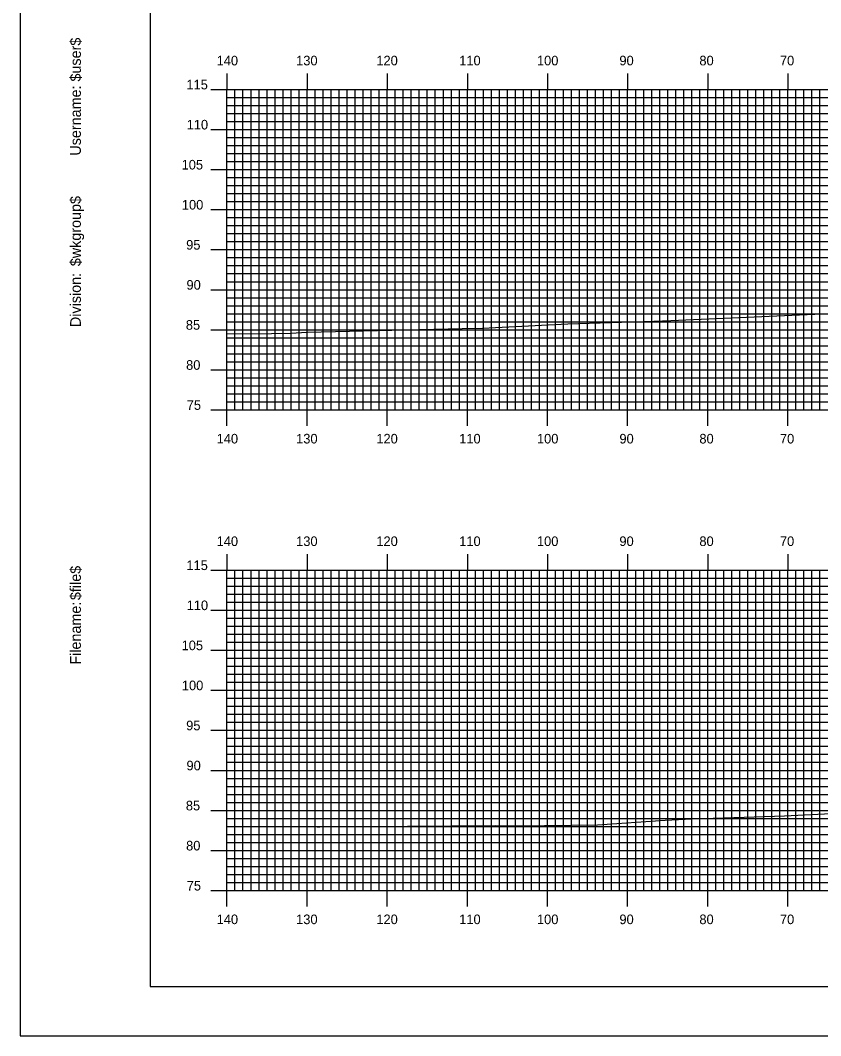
# Model space of a CAD drawing. Extents: x 1760217 to 1760560, y 442591 to 442811.
# Drawn here: x 1760216.9 to 1760316.8, y 442590.5 to 442717.3 of the extents above; entities that cross this region are included whole.
import ezdxf

# ---------------------------------------------------------------- set-up
doc = ezdxf.new("R2010")
doc.units = 0
for name, color, linetype in [('BORDER', 7, 'Continuous'), ('H_V ANNOTATION', 7, 'Continuous'), ('MAJOR', 7, 'Continuous'), ('MINOR', 7, 'Continuous'), ('PLOT BOUNDARY', 7, 'Continuous'), ('S_Roadway_Centerline', 7, 'Continuous')]:
    doc.layers.add(name, color=color, linetype=linetype)

msp = doc.modelspace()

# ---------------------------------------------------------------- linework, layer by layer
at = {"layer": 'BORDER'}
msp.add_lwpolyline([(1760233.1, 442596.67), (1760553.1, 442596.67), (1760553.1, 442806.67), (1760233.1, 442806.67)], close=True, dxfattribs=at)
at = {"layer": 'MAJOR'}
for p, q in [((1760242.7, 442710.67), (1760242.7, 442708.67)), ((1760252.7, 442710.67), (1760252.7, 442708.67)), ((1760262.7, 442710.67), (1760262.7, 442708.67)), ((1760272.7, 442710.67), (1760272.7, 442708.67)), ((1760282.7, 442710.67), (1760282.7, 442708.67)), ((1760292.7, 442710.67), (1760292.7, 442708.67)), ((1760302.7, 442710.67), (1760302.7, 442708.67)), ((1760312.7, 442710.67), (1760312.7, 442708.67)), ((1760240.7, 442708.67), (1760242.7, 442708.67)), ((1760242.7, 442708.67), (1760522.7, 442708.67)), ((1760242.7, 442668.67), (1760242.7, 442708.67)), ((1760242.7, 442668.67), (1760242.7, 442708.67)), ((1760242.7, 442708.67), (1760522.7, 442708.67)), ((1760252.7, 442668.67), (1760252.7, 442708.67)), ((1760262.7, 442668.67), (1760262.7, 442708.67)), ((1760272.7, 442668.67), (1760272.7, 442708.67)), ((1760282.7, 442668.67), (1760282.7, 442708.67)), ((1760292.7, 442668.67), (1760292.7, 442708.67)), ((1760302.7, 442668.67), (1760302.7, 442708.67)), ((1760312.7, 442668.67), (1760312.7, 442708.67)), ((1760240.7, 442703.67), (1760242.7, 442703.67)), ((1760242.7, 442703.67), (1760522.7, 442703.67)), ((1760240.7, 442698.67), (1760242.7, 442698.67)), ((1760242.7, 442698.67), (1760522.7, 442698.67)), ((1760240.7, 442693.67), (1760242.7, 442693.67)), ((1760242.7, 442693.67), (1760522.7, 442693.67)), ((1760240.7, 442688.67), (1760242.7, 442688.67)), ((1760242.7, 442688.67), (1760522.7, 442688.67)), ((1760240.7, 442683.67), (1760242.7, 442683.67)), ((1760242.7, 442683.67), (1760522.7, 442683.67)), ((1760240.7, 442678.67), (1760242.7, 442678.67)), ((1760242.7, 442678.67), (1760522.7, 442678.67)), ((1760240.7, 442673.67), (1760242.7, 442673.67)), ((1760242.7, 442673.67), (1760522.7, 442673.67)), ((1760240.7, 442668.67), (1760242.7, 442668.67)), ((1760242.7, 442668.67), (1760522.7, 442668.67)), ((1760242.7, 442668.67), (1760522.7, 442668.67)), ((1760242.7, 442666.66), (1760242.7, 442668.67)), ((1760252.7, 442666.66), (1760252.7, 442668.67)), ((1760262.7, 442666.66), (1760262.7, 442668.67)), ((1760272.7, 442666.66), (1760272.7, 442668.67)), ((1760282.7, 442666.66), (1760282.7, 442668.67)), ((1760292.7, 442666.66), (1760292.7, 442668.67)), ((1760302.7, 442666.66), (1760302.7, 442668.67)), ((1760312.7, 442666.66), (1760312.7, 442668.67)), ((1760242.7, 442650.67), (1760242.7, 442648.67)), ((1760252.7, 442650.67), (1760252.7, 442648.67)), ((1760262.7, 442650.67), (1760262.7, 442648.67)), ((1760272.7, 442650.67), (1760272.7, 442648.67)), ((1760282.7, 442650.67), (1760282.7, 442648.67)), ((1760292.7, 442650.67), (1760292.7, 442648.67)), ((1760302.7, 442650.67), (1760302.7, 442648.67)), ((1760312.7, 442650.67), (1760312.7, 442648.67)), ((1760240.7, 442648.67), (1760242.7, 442648.67)), ((1760242.7, 442648.67), (1760522.7, 442648.67)), ((1760242.7, 442608.67), (1760242.7, 442648.67)), ((1760242.7, 442608.67), (1760242.7, 442648.67)), ((1760242.7, 442648.67), (1760522.7, 442648.67)), ((1760252.7, 442608.67), (1760252.7, 442648.67)), ((1760262.7, 442608.67), (1760262.7, 442648.67)), ((1760272.7, 442608.67), (1760272.7, 442648.67)), ((1760282.7, 442608.67), (1760282.7, 442648.67)), ((1760292.7, 442608.67), (1760292.7, 442648.67)), ((1760302.7, 442608.67), (1760302.7, 442648.67)), ((1760312.7, 442608.67), (1760312.7, 442648.67)), ((1760240.7, 442643.67), (1760242.7, 442643.67)), ((1760242.7, 442643.67), (1760522.7, 442643.67)), ((1760240.7, 442638.67), (1760242.7, 442638.67)), ((1760242.7, 442638.67), (1760522.7, 442638.67)), ((1760240.7, 442633.67), (1760242.7, 442633.67)), ((1760242.7, 442633.67), (1760522.7, 442633.67)), ((1760240.7, 442628.67), (1760242.7, 442628.67)), ((1760242.7, 442628.67), (1760522.7, 442628.67)), ((1760240.7, 442623.67), (1760242.7, 442623.67)), ((1760242.7, 442623.67), (1760522.7, 442623.67)), ((1760240.7, 442618.67), (1760242.7, 442618.67)), ((1760242.7, 442618.67), (1760522.7, 442618.67)), ((1760240.7, 442613.67), (1760242.7, 442613.67)), ((1760242.7, 442613.67), (1760522.7, 442613.67)), ((1760240.7, 442608.67), (1760242.7, 442608.67)), ((1760242.7, 442608.67), (1760522.7, 442608.67)), ((1760242.7, 442608.67), (1760522.7, 442608.67)), ((1760242.7, 442606.66), (1760242.7, 442608.67)), ((1760252.7, 442606.66), (1760252.7, 442608.67)), ((1760262.7, 442606.66), (1760262.7, 442608.67)), ((1760272.7, 442606.66), (1760272.7, 442608.67)), ((1760282.7, 442606.66), (1760282.7, 442608.67)), ((1760292.7, 442606.66), (1760292.7, 442608.67)), ((1760302.7, 442606.66), (1760302.7, 442608.67)), ((1760312.7, 442606.66), (1760312.7, 442608.67))]:
    msp.add_line(p, q, dxfattribs=at)
at = {"layer": 'MINOR'}
for p, q in [((1760243.7, 442668.67), (1760243.7, 442708.67)), ((1760244.7, 442668.67), (1760244.7, 442708.67)), ((1760245.7, 442668.67), (1760245.7, 442708.67)), ((1760246.7, 442668.67), (1760246.7, 442708.67)), ((1760247.7, 442668.67), (1760247.7, 442708.67)), ((1760248.7, 442668.67), (1760248.7, 442708.67)), ((1760249.7, 442668.67), (1760249.7, 442708.67)), ((1760250.7, 442668.67), (1760250.7, 442708.67)), ((1760251.7, 442668.67), (1760251.7, 442708.67)), ((1760253.7, 442668.67), (1760253.7, 442708.67)), ((1760254.7, 442668.67), (1760254.7, 442708.67)), ((1760255.7, 442668.67), (1760255.7, 442708.67)), ((1760256.7, 442668.67), (1760256.7, 442708.67)), ((1760257.7, 442668.67), (1760257.7, 442708.67)), ((1760258.7, 442668.67), (1760258.7, 442708.67)), ((1760259.7, 442668.67), (1760259.7, 442708.67)), ((1760260.7, 442668.67), (1760260.7, 442708.67)), ((1760261.7, 442668.67), (1760261.7, 442708.67)), ((1760263.7, 442668.67), (1760263.7, 442708.67)), ((1760264.7, 442668.67), (1760264.7, 442708.67)), ((1760265.7, 442668.67), (1760265.7, 442708.67)), ((1760266.7, 442668.67), (1760266.7, 442708.67)), ((1760267.7, 442668.67), (1760267.7, 442708.67)), ((1760268.7, 442668.67), (1760268.7, 442708.67)), ((1760269.7, 442668.67), (1760269.7, 442708.67)), ((1760270.7, 442668.67), (1760270.7, 442708.67)), ((1760271.7, 442668.67), (1760271.7, 442708.67)), ((1760273.7, 442668.67), (1760273.7, 442708.67)), ((1760274.7, 442668.67), (1760274.7, 442708.67)), ((1760275.7, 442668.67), (1760275.7, 442708.67)), ((1760276.7, 442668.67), (1760276.7, 442708.67)), ((1760277.7, 442668.67), (1760277.7, 442708.67)), ((1760278.7, 442668.67), (1760278.7, 442708.67)), ((1760279.7, 442668.67), (1760279.7, 442708.67)), ((1760280.7, 442668.67), (1760280.7, 442708.67)), ((1760281.7, 442668.67), (1760281.7, 442708.67)), ((1760283.7, 442668.67), (1760283.7, 442708.67)), ((1760284.7, 442668.67), (1760284.7, 442708.67)), ((1760285.7, 442668.67), (1760285.7, 442708.67)), ((1760286.7, 442668.67), (1760286.7, 442708.67)), ((1760287.7, 442668.67), (1760287.7, 442708.67)), ((1760288.7, 442668.67), (1760288.7, 442708.67)), ((1760289.7, 442668.67), (1760289.7, 442708.67)), ((1760290.7, 442668.67), (1760290.7, 442708.67)), ((1760291.7, 442668.67), (1760291.7, 442708.67)), ((1760293.7, 442668.67), (1760293.7, 442708.67)), ((1760294.7, 442668.67), (1760294.7, 442708.67)), ((1760295.7, 442668.67), (1760295.7, 442708.67)), ((1760296.7, 442668.67), (1760296.7, 442708.67)), ((1760297.7, 442668.67), (1760297.7, 442708.67)), ((1760298.7, 442668.67), (1760298.7, 442708.67)), ((1760299.7, 442668.67), (1760299.7, 442708.67)), ((1760300.7, 442668.67), (1760300.7, 442708.67)), ((1760301.7, 442668.67), (1760301.7, 442708.67)), ((1760303.7, 442668.67), (1760303.7, 442708.67)), ((1760304.7, 442668.67), (1760304.7, 442708.67)), ((1760305.7, 442668.67), (1760305.7, 442708.67)), ((1760306.7, 442668.67), (1760306.7, 442708.67)), ((1760307.7, 442668.67), (1760307.7, 442708.67)), ((1760308.7, 442668.67), (1760308.7, 442708.67)), ((1760309.7, 442668.67), (1760309.7, 442708.67)), ((1760310.7, 442668.67), (1760310.7, 442708.67)), ((1760311.7, 442668.67), (1760311.7, 442708.67)), ((1760313.7, 442668.67), (1760313.7, 442708.67)), ((1760314.7, 442668.67), (1760314.7, 442708.67)), ((1760315.7, 442668.67), (1760315.7, 442708.67)), ((1760316.7, 442668.67), (1760316.7, 442708.67)), ((1760242.7, 442707.67), (1760522.7, 442707.67)), ((1760242.7, 442707.67), (1760244.7, 442707.67)), ((1760242.7, 442706.67), (1760522.7, 442706.67)), ((1760242.7, 442706.67), (1760244.7, 442706.67)), ((1760242.7, 442705.67), (1760522.7, 442705.67)), ((1760242.7, 442705.67), (1760244.7, 442705.67)), ((1760242.7, 442704.67), (1760522.7, 442704.67)), ((1760242.7, 442704.67), (1760244.7, 442704.67)), ((1760242.7, 442702.67), (1760522.7, 442702.67)), ((1760242.7, 442702.67), (1760244.7, 442702.67)), ((1760242.7, 442701.67), (1760522.7, 442701.67)), ((1760242.7, 442701.67), (1760244.7, 442701.67)), ((1760242.7, 442700.67), (1760522.7, 442700.67)), ((1760242.7, 442700.67), (1760244.7, 442700.67)), ((1760242.7, 442699.67), (1760522.7, 442699.67)), ((1760242.7, 442699.67), (1760244.7, 442699.67)), ((1760242.7, 442697.67), (1760522.7, 442697.67)), ((1760242.7, 442697.67), (1760244.7, 442697.67)), ((1760242.7, 442696.67), (1760522.7, 442696.67)), ((1760242.7, 442696.67), (1760244.7, 442696.67)), ((1760242.7, 442695.67), (1760522.7, 442695.67)), ((1760242.7, 442695.67), (1760244.7, 442695.67)), ((1760242.7, 442694.67), (1760522.7, 442694.67)), ((1760242.7, 442694.67), (1760244.7, 442694.67)), ((1760242.7, 442692.67), (1760522.7, 442692.67)), ((1760242.7, 442692.67), (1760244.7, 442692.67)), ((1760242.7, 442691.67), (1760522.7, 442691.67)), ((1760242.7, 442691.67), (1760244.7, 442691.67)), ((1760242.7, 442690.67), (1760522.7, 442690.67)), ((1760242.7, 442690.67), (1760244.7, 442690.67)), ((1760242.7, 442689.67), (1760522.7, 442689.67)), ((1760242.7, 442689.67), (1760244.7, 442689.67)), ((1760242.7, 442687.67), (1760522.7, 442687.67)), ((1760242.7, 442687.67), (1760244.7, 442687.67)), ((1760242.7, 442686.67), (1760522.7, 442686.67)), ((1760242.7, 442686.67), (1760244.7, 442686.67)), ((1760242.7, 442685.67), (1760522.7, 442685.67)), ((1760242.7, 442685.67), (1760244.7, 442685.67)), ((1760242.7, 442684.67), (1760522.7, 442684.67)), ((1760242.7, 442684.67), (1760244.7, 442684.67)), ((1760242.7, 442682.67), (1760522.7, 442682.67)), ((1760242.7, 442682.67), (1760244.7, 442682.67)), ((1760242.7, 442681.67), (1760522.7, 442681.67)), ((1760242.7, 442681.67), (1760244.7, 442681.67)), ((1760242.7, 442680.67), (1760522.7, 442680.67)), ((1760242.7, 442680.67), (1760244.7, 442680.67)), ((1760242.7, 442679.67), (1760522.7, 442679.67)), ((1760242.7, 442679.67), (1760244.7, 442679.67)), ((1760242.7, 442677.67), (1760522.7, 442677.67)), ((1760242.7, 442677.67), (1760244.7, 442677.67)), ((1760242.7, 442676.67), (1760522.7, 442676.67)), ((1760242.7, 442676.67), (1760244.7, 442676.67)), ((1760242.7, 442675.67), (1760522.7, 442675.67)), ((1760242.7, 442675.67), (1760244.7, 442675.67)), ((1760242.7, 442674.67), (1760522.7, 442674.67)), ((1760242.7, 442674.67), (1760244.7, 442674.67)), ((1760242.7, 442672.67), (1760522.7, 442672.67)), ((1760242.7, 442672.67), (1760244.7, 442672.67)), ((1760242.7, 442671.67), (1760522.7, 442671.67)), ((1760242.7, 442671.67), (1760244.7, 442671.67)), ((1760242.7, 442670.67), (1760522.7, 442670.67)), ((1760242.7, 442670.67), (1760244.7, 442670.67)), ((1760242.7, 442669.67), (1760522.7, 442669.67)), ((1760242.7, 442669.67), (1760244.7, 442669.67)), ((1760243.7, 442608.67), (1760243.7, 442648.67)), ((1760244.7, 442608.67), (1760244.7, 442648.67)), ((1760245.7, 442608.67), (1760245.7, 442648.67)), ((1760246.7, 442608.67), (1760246.7, 442648.67)), ((1760247.7, 442608.67), (1760247.7, 442648.67)), ((1760248.7, 442608.67), (1760248.7, 442648.67)), ((1760249.7, 442608.67), (1760249.7, 442648.67)), ((1760250.7, 442608.67), (1760250.7, 442648.67)), ((1760251.7, 442608.67), (1760251.7, 442648.67)), ((1760253.7, 442608.67), (1760253.7, 442648.67)), ((1760254.7, 442608.67), (1760254.7, 442648.67)), ((1760255.7, 442608.67), (1760255.7, 442648.67)), ((1760256.7, 442608.67), (1760256.7, 442648.67)), ((1760257.7, 442608.67), (1760257.7, 442648.67)), ((1760258.7, 442608.67), (1760258.7, 442648.67)), ((1760259.7, 442608.67), (1760259.7, 442648.67)), ((1760260.7, 442608.67), (1760260.7, 442648.67)), ((1760261.7, 442608.67), (1760261.7, 442648.67)), ((1760263.7, 442608.67), (1760263.7, 442648.67)), ((1760264.7, 442608.67), (1760264.7, 442648.67)), ((1760265.7, 442608.67), (1760265.7, 442648.67)), ((1760266.7, 442608.67), (1760266.7, 442648.67)), ((1760267.7, 442608.67), (1760267.7, 442648.67)), ((1760268.7, 442608.67), (1760268.7, 442648.67)), ((1760269.7, 442608.67), (1760269.7, 442648.67)), ((1760270.7, 442608.67), (1760270.7, 442648.67)), ((1760271.7, 442608.67), (1760271.7, 442648.67)), ((1760273.7, 442608.67), (1760273.7, 442648.67)), ((1760274.7, 442608.67), (1760274.7, 442648.67)), ((1760275.7, 442608.67), (1760275.7, 442648.67)), ((1760276.7, 442608.67), (1760276.7, 442648.67)), ((1760277.7, 442608.67), (1760277.7, 442648.67)), ((1760278.7, 442608.67), (1760278.7, 442648.67)), ((1760279.7, 442608.67), (1760279.7, 442648.67)), ((1760280.7, 442608.67), (1760280.7, 442648.67)), ((1760281.7, 442608.67), (1760281.7, 442648.67)), ((1760283.7, 442608.67), (1760283.7, 442648.67)), ((1760284.7, 442608.67), (1760284.7, 442648.67)), ((1760285.7, 442608.67), (1760285.7, 442648.67)), ((1760286.7, 442608.67), (1760286.7, 442648.67)), ((1760287.7, 442608.67), (1760287.7, 442648.67)), ((1760288.7, 442608.67), (1760288.7, 442648.67)), ((1760289.7, 442608.67), (1760289.7, 442648.67)), ((1760290.7, 442608.67), (1760290.7, 442648.67)), ((1760291.7, 442608.67), (1760291.7, 442648.67)), ((1760293.7, 442608.67), (1760293.7, 442648.67)), ((1760294.7, 442608.67), (1760294.7, 442648.67)), ((1760295.7, 442608.67), (1760295.7, 442648.67)), ((1760296.7, 442608.67), (1760296.7, 442648.67)), ((1760297.7, 442608.67), (1760297.7, 442648.67)), ((1760298.7, 442608.67), (1760298.7, 442648.67)), ((1760299.7, 442608.67), (1760299.7, 442648.67)), ((1760300.7, 442608.67), (1760300.7, 442648.67)), ((1760301.7, 442608.67), (1760301.7, 442648.67)), ((1760303.7, 442608.67), (1760303.7, 442648.67)), ((1760304.7, 442608.67), (1760304.7, 442648.67)), ((1760305.7, 442608.67), (1760305.7, 442648.67)), ((1760306.7, 442608.67), (1760306.7, 442648.67)), ((1760307.7, 442608.67), (1760307.7, 442648.67)), ((1760308.7, 442608.67), (1760308.7, 442648.67)), ((1760309.7, 442608.67), (1760309.7, 442648.67)), ((1760310.7, 442608.67), (1760310.7, 442648.67)), ((1760311.7, 442608.67), (1760311.7, 442648.67)), ((1760313.7, 442608.67), (1760313.7, 442648.67)), ((1760314.7, 442608.67), (1760314.7, 442648.67)), ((1760315.7, 442608.67), (1760315.7, 442648.67)), ((1760316.7, 442608.67), (1760316.7, 442648.67)), ((1760242.7, 442647.67), (1760522.7, 442647.67)), ((1760242.7, 442647.67), (1760244.7, 442647.67)), ((1760242.7, 442646.67), (1760522.7, 442646.67)), ((1760242.7, 442646.67), (1760244.7, 442646.67)), ((1760242.7, 442645.67), (1760522.7, 442645.67)), ((1760242.7, 442645.67), (1760244.7, 442645.67)), ((1760242.7, 442644.67), (1760522.7, 442644.67)), ((1760242.7, 442644.67), (1760244.7, 442644.67)), ((1760242.7, 442642.67), (1760522.7, 442642.67)), ((1760242.7, 442642.67), (1760244.7, 442642.67)), ((1760242.7, 442641.67), (1760522.7, 442641.67)), ((1760242.7, 442641.67), (1760244.7, 442641.67)), ((1760242.7, 442640.67), (1760522.7, 442640.67)), ((1760242.7, 442640.67), (1760244.7, 442640.67)), ((1760242.7, 442639.67), (1760522.7, 442639.67)), ((1760242.7, 442639.67), (1760244.7, 442639.67)), ((1760242.7, 442637.67), (1760522.7, 442637.67)), ((1760242.7, 442637.67), (1760244.7, 442637.67)), ((1760242.7, 442636.67), (1760522.7, 442636.67)), ((1760242.7, 442636.67), (1760244.7, 442636.67)), ((1760242.7, 442635.67), (1760522.7, 442635.67)), ((1760242.7, 442635.67), (1760244.7, 442635.67)), ((1760242.7, 442634.67), (1760522.7, 442634.67)), ((1760242.7, 442634.67), (1760244.7, 442634.67)), ((1760242.7, 442632.67), (1760522.7, 442632.67)), ((1760242.7, 442632.67), (1760244.7, 442632.67)), ((1760242.7, 442631.67), (1760522.7, 442631.67)), ((1760242.7, 442631.67), (1760244.7, 442631.67)), ((1760242.7, 442630.67), (1760522.7, 442630.67)), ((1760242.7, 442630.67), (1760244.7, 442630.67)), ((1760242.7, 442629.67), (1760522.7, 442629.67)), ((1760242.7, 442629.67), (1760244.7, 442629.67)), ((1760242.7, 442627.67), (1760522.7, 442627.67)), ((1760242.7, 442627.67), (1760244.7, 442627.67)), ((1760242.7, 442626.67), (1760522.7, 442626.67)), ((1760242.7, 442626.67), (1760244.7, 442626.67)), ((1760242.7, 442625.67), (1760522.7, 442625.67)), ((1760242.7, 442625.67), (1760244.7, 442625.67)), ((1760242.7, 442624.67), (1760522.7, 442624.67)), ((1760242.7, 442624.67), (1760244.7, 442624.67)), ((1760242.7, 442622.67), (1760522.7, 442622.67)), ((1760242.7, 442622.67), (1760244.7, 442622.67)), ((1760242.7, 442621.67), (1760522.7, 442621.67)), ((1760242.7, 442621.67), (1760244.7, 442621.67)), ((1760242.7, 442620.67), (1760522.7, 442620.67)), ((1760242.7, 442620.67), (1760244.7, 442620.67)), ((1760242.7, 442619.67), (1760522.7, 442619.67)), ((1760242.7, 442619.67), (1760244.7, 442619.67)), ((1760242.7, 442617.67), (1760522.7, 442617.67)), ((1760242.7, 442617.67), (1760244.7, 442617.67)), ((1760242.7, 442616.67), (1760522.7, 442616.67)), ((1760242.7, 442616.67), (1760244.7, 442616.67)), ((1760242.7, 442615.67), (1760522.7, 442615.67)), ((1760242.7, 442615.67), (1760244.7, 442615.67)), ((1760242.7, 442614.67), (1760522.7, 442614.67)), ((1760242.7, 442614.67), (1760244.7, 442614.67)), ((1760242.7, 442612.67), (1760522.7, 442612.67)), ((1760242.7, 442612.67), (1760244.7, 442612.67)), ((1760242.7, 442611.67), (1760522.7, 442611.67)), ((1760242.7, 442611.67), (1760244.7, 442611.67)), ((1760242.7, 442610.67), (1760522.7, 442610.67)), ((1760242.7, 442610.67), (1760244.7, 442610.67)), ((1760242.7, 442609.67), (1760522.7, 442609.67)), ((1760242.7, 442609.67), (1760244.7, 442609.67))]:
    msp.add_line(p, q, dxfattribs=at)
at = {"layer": 'PLOT BOUNDARY'}
msp.add_lwpolyline([(1760216.91, 442590.55), (1760556.91, 442590.55), (1760556.91, 442810.55), (1760216.91, 442810.55)], close=True, dxfattribs=at)
at = {"layer": 'S_Roadway_Centerline'}
for points in [[(1760242.7, 442678.14), (1760248.26, 442678.2), (1760250.62, 442678.24), (1760252.71, 442678.35), (1760272.05, 442678.81), (1760274.59, 442678.87), (1760285.24, 442679.42), (1760295.98, 442679.76), (1760298.09, 442679.84), (1760317.91, 442680.69)], [(1760242.7, 442616.67), (1760243.23, 442616.68), (1760253.95, 442616.61), (1760253.99, 442616.61), (1760254.28, 442616.61), (1760276.15, 442616.79), (1760278.98, 442616.76), (1760288.92, 442616.85), (1760297.37, 442617.45), (1760300.72, 442617.63), (1760304.7, 442617.74), (1760312.28, 442618.01), (1760318.93, 442618.31)]]:
    msp.add_lwpolyline(points, dxfattribs=at)

# ---------------------------------------------------------------- texts
at = {"layer": 'BORDER'}
for s, p in [('$user$', (1760224.47, 442709.65)), ('Username:', (1760224.47, 442700.4)), ('$wkgroup$', (1760224.47, 442686.6)), ('Division:', (1760224.47, 442679)), ('$file$', (1760224.47, 442644.92)), ('Filename:', (1760224.47, 442636.86))]:
    msp.add_text(s, height=1.339, rotation=90, dxfattribs=at).set_placement(p)
at = {"layer": 'H_V ANNOTATION'}
for s, p in [('140', (1760241.41, 442711.67)), ('130', (1760251.33, 442711.67)), ('120', (1760261.34, 442711.67)), ('110', (1760271.68, 442711.67)), ('100', (1760281.38, 442711.67)), ('90', (1760291.67, 442711.67)), ('80', (1760301.65, 442711.67)), ('70', (1760311.7, 442711.67)), ('115', (1760237.64, 442708.67)), ('110', (1760237.67, 442703.67)), ('105', (1760237.04, 442698.67)), ('100', (1760237.07, 442693.67)), ('95', (1760237.61, 442688.67)), ('90', (1760237.65, 442683.67)), ('85', (1760237.57, 442678.67)), ('80', (1760237.6, 442673.67)), ('75', (1760237.68, 442668.67)), ('140', (1760241.41, 442664.47)), ('130', (1760251.33, 442664.47)), ('120', (1760261.34, 442664.47)), ('110', (1760271.68, 442664.47)), ('100', (1760281.38, 442664.47)), ('90', (1760291.67, 442664.47)), ('80', (1760301.65, 442664.47)), ('70', (1760311.7, 442664.47)), ('140', (1760241.41, 442651.67)), ('130', (1760251.33, 442651.67)), ('120', (1760261.34, 442651.67)), ('110', (1760271.68, 442651.67)), ('100', (1760281.38, 442651.67)), ('90', (1760291.67, 442651.67)), ('80', (1760301.65, 442651.67)), ('70', (1760311.7, 442651.67)), ('115', (1760237.64, 442648.67)), ('110', (1760237.67, 442643.67)), ('105', (1760237.04, 442638.67)), ('100', (1760237.07, 442633.67)), ('95', (1760237.61, 442628.67)), ('90', (1760237.65, 442623.67)), ('85', (1760237.57, 442618.67)), ('80', (1760237.6, 442613.67)), ('75', (1760237.68, 442608.67)), ('140', (1760241.41, 442604.47)), ('130', (1760251.33, 442604.47)), ('120', (1760261.34, 442604.47)), ('110', (1760271.68, 442604.47)), ('100', (1760281.38, 442604.47)), ('90', (1760291.67, 442604.47)), ('80', (1760301.65, 442604.47)), ('70', (1760311.7, 442604.47))]:
    msp.add_text(s, height=1.2, dxfattribs=at).set_placement(p)
at = {"layer": 'MAJOR'}
for p in [(1760242.69, 442668.67), (1760242.69, 442608.67)]:
    msp.add_text('-', height=0.012, dxfattribs=at).set_placement(p)

doc.saveas('drawing.dxf')
